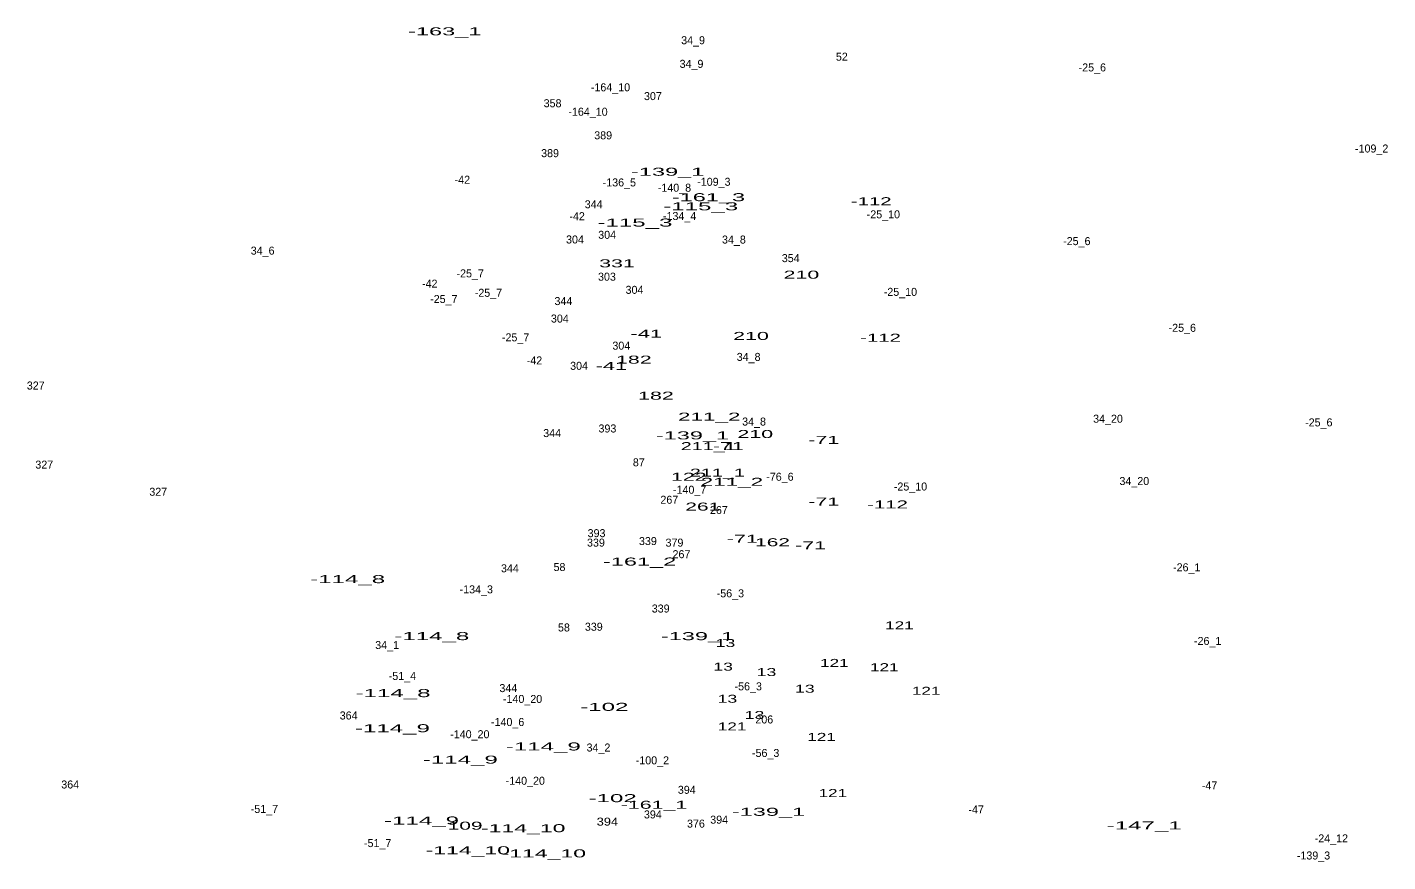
# Model space of a CAD drawing. Extents: x -662499 to -659675, y -1001682 to -998165.
# Drawn here: x -661759 to -661079, y -1000814 to -1000397 of the extents above; entities that cross this region are included whole.
import ezdxf
from ezdxf.enums import TextEntityAlignment as Align

# ---------------------------------------------------------------- set-up
doc = ezdxf.new("R2010")
doc.units = 0
doc.header["$LTSCALE"] = 1.6
doc.layers.add('24', color=7, linetype='Continuous')

msp = doc.modelspace()

# ---------------------------------------------------------------- texts
at = {"layer": '24'}
for s, width, p in [('-163_1', 2.2, (-661550.173, -1000400.76)), ('-139_1', 2.2, (-661438.703, -1000471)), ('-115_3', 2.25, (-661422.187, -1000488.29)), ('-161_3', 2.2, (-661418.303, -1000483.73)), ('-112', 1.9, (-661336.937, -1000485.76)), ('-115_3', 2.25, (-661455.057, -1000496.42)), ('331', 2, (-661464.057, -1000516.81)), ('210', 2, (-661371.844, -1000522.49)), ('-41', 2.05, (-661449.396, -1000552)), ('210', 2, (-661397.044, -1000553.13)), ('-112', 1.9, (-661332.287, -1000554.03)), ('182', 2, (-661455.627, -1000564.99)), ('-41', 2.05, (-661466.846, -1000568.1)), ('182', 2, (-661444.577, -1000583.02)), ('211_2', 2.1, (-661417.935, -1000593.51)), ('-139_1', 2.2, (-661426.303, -1000602.88)), ('210', 2, (-661394.914, -1000602.2)), ('-71', 2, (-661360.665, -1000605.14)), ('211_1', 1.85, (-661418.411, -1000608.25)), ('-71', 2, (-661408.355, -1000608.24)), ('122', 2, (-661428.147, -1000623.57)), ('211_1', 1.85, (-661413.851, -1000621.53)), ('211_2', 2.1, (-661406.595, -1000626.09)), ('261', 1.95, (-661421.153, -1000638.49)), ('-71', 2, (-661360.665, -1000635.98)), ('-112', 1.9, (-661328.797, -1000637.42)), ('-71', 2, (-661401.375, -1000654.6)), ('162', 1.95, (-661386.273, -1000656.33)), ('-71', 2, (-661367.255, -1000657.89)), ('-161_2', 2.2, (-661452.723, -1000666)), ('-114_8', 2.25, (-661598.693, -1000674.78)), ('121', 1.6, (-661322.844, -1000697.9)), ('-114_8', 2.25, (-661556.623, -1000703.28)), ('-139_1', 2.2, (-661423.783, -1000703.31)), ('13', 1.65, (-661409.817, -1000706.73)), ('13', 1.65, (-661410.977, -1000718.55)), ('13', 1.65, (-661389.297, -1000721.26)), ('121', 1.6, (-661355.374, -1000716.69)), ('121', 1.6, (-661330.394, -1000718.82)), ('-114_8', 2.25, (-661576.003, -1000731.79)), ('13', 1.65, (-661408.847, -1000734.62)), ('13', 1.65, (-661370.127, -1000729.59)), ('121', 1.6, (-661309.484, -1000730.64)), ('-102', 2.25, (-661470.367, -1000738.67)), ('121', 1.6, (-661406.494, -1000748.46)), ('13', 1.65, (-661395.297, -1000742.76)), ('-114_9', 2.25, (-661576.298, -1000749.36)), ('121', 1.6, (-661361.764, -1000753.69)), ('-114_9', 2.25, (-661500.878, -1000758.48)), ('-114_9', 2.25, (-661542.368, -1000765.07)), ('121', 1.6, (-661356.144, -1000781.78)), ('-102', 2.25, (-661466.207, -1000784.34)), ('-161_1', 2, (-661445.529, -1000787.64)), ('-114_9', 2.25, (-661561.758, -1000795.52)), ('394', 1.2, (-661468.84, -1000796.07)), ('-139_1', 2.2, (-661388.303, -1000791.16)), ('109', 1.95, (-661539.969, -1000798.11)), ('-114_10', 2.15, (-661510.916, -1000799.36)), ('-147_1', 2.25, (-661200.468, -1000797.96)), ('-114_10', 2.15, (-661538.636, -1000810.41)), ('-114_10', 2.15, (-661500.636, -1000811.97))]:
    msp.add_text(s, height=4, dxfattribs=dict(at, width=width)).set_placement(p, align=Align.CENTER)
for s, p in [('34_9', (-661426.004, -1000405.22)), ('52', (-661351.637, -1000413.45)), ('34_9', (-661426.784, -1000417.03)), ('-25_6', (-661226.408, -1000418.82)), ('-164_10', (-661467.293, -1000428.76)), ('307', (-661446.077, -1000433.16)), ('358', (-661496.247, -1000436.74)), ('-164_10', (-661478.533, -1000440.98)), ('389', (-661470.953, -1000452.78)), ('389', (-661497.513, -1000461.7)), ('-109_2', (-661086.746, -1000459.38)), ('-42', (-661541.359, -1000475.01)), ('-136_5', (-661462.872, -1000476.35)), ('-109_3', (-661415.616, -1000476.02)), ('-140_8', (-661435.314, -1000479)), ('344', (-661475.716, -1000487.28)), ('-42', (-661483.979, -1000493.24)), ('-134_4', (-661432.735, -1000493.14)), ('-25_10', (-661330.88, -1000492.3)), ('304', (-661468.965, -1000502.55)), ('34_6', (-661641.204, -1000510.46)), ('304', (-661485.055, -1000504.88)), ('34_8', (-661405.59, -1000504.92)), ('-25_6', (-661234.158, -1000505.71)), ('354', (-661377.191, -1000514.21)), ('-25_7', (-661537.428, -1000521.85)), ('303', (-661469.061, -1000523.5)), ('-42', (-661557.649, -1000526.98)), ('304', (-661455.295, -1000530.07)), ('-25_7', (-661550.608, -1000534.65)), ('-25_7', (-661528.308, -1000531.55)), ('344', (-661490.836, -1000535.7)), ('-25_10', (-661322.35, -1000531.09)), ('304', (-661492.615, -1000544.44)), ('-25_6', (-661181.428, -1000549.06)), ('-25_7', (-661514.738, -1000553.85)), ('304', (-661461.885, -1000558)), ('34_8', (-661398.23, -1000563.62)), ('-42', (-661505.299, -1000565.38)), ('304', (-661483.015, -1000568.08)), ('327', (-661754.643, -1000577.94)), ('34_8', (-661395.52, -1000595.96)), ('34_20', (-661218.564, -1000594.54)), ('-25_6', (-661113.188, -1000596.38)), ('344', (-661496.456, -1000601.72)), ('393', (-661468.833, -1000599.42)), ('327', (-661750.373, -1000617.5)), ('87', (-661453.143, -1000616.36)), ('-76_6', (-661382.588, -1000623.57)), ('34_20', (-661205.404, -1000625.72)), ('327', (-661693.383, -1000631.07)), ('-140_7', (-661427.73, -1000630.06)), ('-25_10', (-661317.31, -1000628.45)), ('267', (-661437.878, -1000635.07)), ('267', (-661413.108, -1000640.21)), ('393', (-661474.263, -1000651.79)), ('339', (-661474.573, -1000656.51)), ('339', (-661448.593, -1000655.74)), ('379', (-661435.308, -1000656.52)), ('267', (-661431.818, -1000662.31)), ('344', (-661517.586, -1000669.36)), ('58', (-661492.797, -1000668.74)), ('-26_1', (-661179.202, -1000668.86)), ('-134_3', (-661534.39, -1000679.9)), ('-56_3', (-661407.358, -1000681.88)), ('339', (-661442.203, -1000689.48)), ('58', (-661490.567, -1000698.96)), ('339', (-661475.643, -1000698.59)), ('34_1', (-661578.963, -1000707.73)), ('-26_1', (-661168.732, -1000705.71)), ('-51_4', (-661571.32, -1000723.21)), ('344', (-661518.366, -1000729.29)), ('-140_20', (-661511.247, -1000734.71)), ('-56_3', (-661398.438, -1000728.4)), ('364', (-661598.207, -1000742.98)), ('-140_6', (-661518.72, -1000746.25)), ('206', (-661390.407, -1000744.97)), ('-140_20', (-661537.617, -1000752.36)), ('34_2', (-661473.3, -1000759.01)), ('-56_3', (-661389.718, -1000761.73)), ('-100_2', (-661446.344, -1000765.43)), ('-140_20', (-661509.897, -1000775.63)), ('364', (-661737.407, -1000777.5)), ('394', (-661429.157, -1000780.16)), ('-47', (-661167.785, -1000777.99)), ('-51_7', (-661640.312, -1000789.74)), ('394', (-661446.117, -1000792.48)), ('394', (-661412.967, -1000795.1)), ('-47', (-661284.495, -1000790.01)), ('376', (-661424.588, -1000797.07)), ('-51_7', (-661583.702, -1000806.81)), ('-24_12', (-661106.9, -1000804.45)), ('-139_3', (-661115.822, -1000813.02))]:
    msp.add_text(s, height=4, dxfattribs=at).set_placement(p, align=Align.CENTER)

doc.saveas('drawing.dxf')
